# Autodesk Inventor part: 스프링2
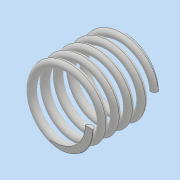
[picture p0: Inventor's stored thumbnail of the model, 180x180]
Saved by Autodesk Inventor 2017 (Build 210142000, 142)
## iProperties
Part Number: 스프링2
Material: 일반
Document SubType Name: Modeling
Designer: MRC
Density: 1 g/cm^3
Appearance: 기본값
Mass: 0.819704 g
Surface Area: 16.7052 cm^2
Volume: 0.819704 cm^3
Author: MRC
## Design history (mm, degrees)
sketch "스케치1"
  geometry: L1 (0, 0)-(0, 17.5); L2 (0, 17.5)-(20.921, 17.5); L3 (0, 0)-(8.5, 0); C1 r 1 at (8.5, 0)
  constraints: 6 end point, 2 horizontal, 1 centre point, 1 coincident, 1 vertical
  dimensions: "d0" = 17.5 distance of L1.start L1.end (derived); "d1" = 8.5 distance of L1.start L3.end; "d2" = 2 diameter of C1
feature "코일1" sketch "스케치1" pitch "d3" = 10; turns "d5" = 5; dims "d4" = 17.5 (= d0), "d6" = 0, angle "d7" = 90 deg, angle "d8" = 90 deg, "d9" = 0, "d10" = 0
sketch "스케치2"
  geometry: L1 (17.5, 11.939)-(0, 11.939); L2 (0, 11.939)-(0, -12.02); L3 (0, -12.02)-(17.5, -12.02); L4 (17.5, -12.02)-(17.5, 11.939); 1 further point
  constraints: 8 end point, 2 parallel, 1 horizontal, 1 perpendicular, 1 point on line
  dimensions: "d11" = 17.5 distance of L2.end L3.end (= d0)
extrude "돌출1" sketch "스케치2" stored distance "d12" = 0; taper "d13" = 0 deg
node "솔리드1"
